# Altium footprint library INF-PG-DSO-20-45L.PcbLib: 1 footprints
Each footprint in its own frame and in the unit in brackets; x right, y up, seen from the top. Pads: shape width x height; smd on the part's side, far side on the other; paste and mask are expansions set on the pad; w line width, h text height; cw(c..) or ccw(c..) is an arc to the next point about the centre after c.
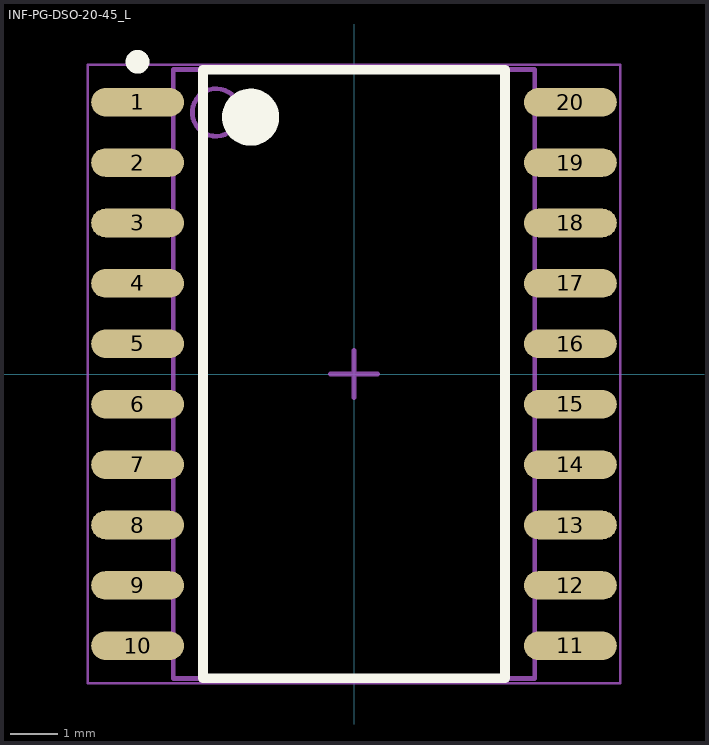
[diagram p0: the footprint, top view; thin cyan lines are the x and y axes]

## INF-PG-DSO-20-45_L [mm] "SOP, 20-Leads, Body 12.7x7.5mm, Pitch 1.27mm, IPC High Density"
height 2.65
pads (20):
  oval 1.95x0.6 smd: 1(-4.55,5.715) 2(-4.55,4.445) 3(-4.55,3.175) 4(-4.55,1.905) 5(-4.55,0.635) 6(-4.55,-0.635) 7(-4.55,-1.905) 8(-4.55,-3.175) 9(-4.55,-4.445) 10(-4.55,-5.715) 11(4.55,-5.715) 12(4.55,-4.445) 13(4.55,-3.175) 14(4.55,-1.905) 15(4.55,-0.635) 16(4.55,0.635) 17(4.55,1.905) 18(4.55,3.175) 19(4.55,4.445) 20(4.55,5.715)
Top Overlay:
  circle w0.25: c-4.55,6.565 r0.125
  circle w0.6: c-2.175,5.4 r0.3
  lines w0.2: -3.175,-6.4 -3.175,6.4 3.175,6.4 3.175,-6.4 -3.175,-6.4
Mechanical 13:
  circle w0.1: c-2.9,5.5 r0.5
  lines w0.1: -3.8,-6.4 -3.8,6.4 3.8,6.4 3.8,-6.4 -3.8,-6.4
Mechanical 15:
  lines w0.05: -5.6,-6.5 -5.6,6.5 5.6,6.5 5.6,-6.5 -5.6,-6.5
  lines w0.1: -0.5,0 0.5,0 ; 0,-0.5 0,0.5
3D body: height 2.65, standoff 0.1, extent -3.8,-6.4 3.8,6.4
